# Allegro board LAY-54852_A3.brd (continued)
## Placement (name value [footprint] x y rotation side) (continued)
R1747  10K  [0402_CC]  12.98 62.38 180 top
R1748  1K  [0402_CC]  6.18 68.93 180 top
R1749  0  [0402_CC]  18.67 66.45 180 top
R1750  10K  [0402_CC]  18.67 67.55 0 top
R1751  100  [RC0402_25]  15.26 70.46 180 top
R1752  0  [0402_CC]  6.17 67.77 0 top
R1753  10K  [0402_CC]  13.27 70.44 180 top
R1754  10K  [0402_CC]  6.17 66.59 180 top
R1755  0  [0402_CC]  13.27 69.33 180 top
R1756  22K  [0402_CC]  27.43 54.38 90 top
R1757  0  [0805_CC]  44.99 23.93 180 top
R1758  100K  [0402_CC]  50.08 20.93 180 top
R1759  100K  [0402_CC]  50.08 24.58 0 top
R1760  10K  [0402_CC]  70.29 17.17 90 top
R1761  100K  [0402_CC]  71.4 17.16 270 top
R1762  10K  [0402_CC]  52.37 21.33 90 top
R1763  100K  [0402_CC]  53.68 21.32 90 top
R1764  0  [0402_CC]  68.41 10.11 270 top
R1765  10K  [0402_CC]  67.27 10.09 90 top
R1766  1.2M  [0402_CC]  24.39 36 90 top
R1767  10K  [0402_CC]  79.56 63.2 0 top
R1768  1K  [0402_CC]  24.78 29.61 90 top
R1769  1M  [0402_CC]  26.94 29.6 90 top
R1770  47K  [0603_CC]  26.8 27.54 270 top
R1771  324K  [0402_CC]  25.86 29.61 270 top
R1772  249K  [0402_CC]  25.76 36.03 90 top
R1773  0  [0805_CC]  23.34 16.3 180 top
R1774  0  [0805_CC]  23.29 18.41 180 top
R1775  10K  [0402_CC]  36.98 21.02 270 top
R1776  0  [0402_CC]  30.7 16.02 180 top
R1777  0  [0402_CC]  41.45 18.19 0 top
R1778  0  [0402_CC]  41.45 16.96 0 top
R1779  1.5K  [0402_CC]  95.76 30.99 180 top
R1780  0  [0402_CC]  93.68 30.99 180 top
R1781  10K  [0402_CC]  128.73 30.79 180 top
R1782  41.2K  [RC0402_25]  128.81 36.81 90 top
R1783  100K  [0402_CC]  130.78 30.47 90 top
R1784  0  [0402_CC]  129.64 27.17 270 top
R1785  0  [0402_CC]  128.54 27.18 270 top
R1786  0  [0402_CC]  127.44 27.16 270 top
R1790  1K  [0402_CC]  133.42 20.38 180 top
R1791  1K  [0402_CC]  131.14 19.53 90 top
R1793  0  [0402_CC]  127.97 4.34 90 top
R1795  0  [0402_CC]  107.78 32.49 180 top
R1798  20  [0603_CC]  101.67 20.44 180 top
R1800  0  [0402_CC]  104.35 23.82 270 top
R1801  20  [0603_CC]  106.36 20.3 0 top
R1809  2.20K  [0603_CC]  108.39 16.1 180 top
R1810  10K  [0402_CC]  105.12 18.05 0 top
R1812  120K  [0402_CC]  118.84 29.08 0 bottom
R1813  10K  [0402_CC]  134.34 27.04 0 top
R1814  0  [0402_CC]  10.45 72.17 180 top
R1815  10K  [0402_CC]  8.42 69.88 0 top
R1816  10K  [0402_CC]  10.38 59.14 90 top
R1817  0  [0402_CC]  10.67 45.71 90 top
R1818  0  [0402_CC]  9.6 45.7 90 top
R1819  0  [0402_CC]  8.51 45.68 90 top
R1820  0  [0402_CC]  7.45 45.67 90 top
R1821  10K  [0402_CC]  11.76 45.71 270 top
R1822  0  [0402_CC]  98.4 15.94 270 top
R1823  10K  [0402_CC]  103 18.12 180 top
R1824  10K  [0402_CC]  99.39 76.8 270 bottom
R1825  0  [0402_CC]  100.48 76.81 90 bottom
R1827  10K  [0402_CC]  74.58 71.97 0 top
R1829  0  [0402_CC]  130.9 82.07 0 bottom
S1501  CHS-01TA1  [SW_2P8X5P7_SM]  42.15 61.96 270 top
SW301  M096H-A020RT21A  [SW6_DPDT_M096H_TH]  69.5 1.5 180 top
SW601  CHS-04TA  [SW_CHS_04_A]  41.14 52.96 0 top
SW1401  TL6330AF200Q  [SW4_SPST_4P6X2P8_SM]  26.35 81.54 0 top
SW1402  TL6330AF200Q  [SW4_SPST_4P6X2P8_SM]  33.23 81.54 0 top
TP45  -  [TPAD_050]  76.52 71.99 180 top
TP201  -  [TPAD_015]  79.34 53.58 0 top
TP202  -  [TPAD_015]  79.26 54.27 0 top
TP203  -  [TPAD_015]  79.16 54.84 0 top
TP204  -  [TPAD_015]  79.11 55.47 0 top
TP205  -  [TPAD_015]  79.98 54.99 0 top
TP206  -  [TPAD_015]  79.22 51.44 0 top
TP207  -  [TPAD_015]  79.69 51.98 0 top
TP208  -  [TPAD_015]  79.16 52.48 0 top
TP209  -  [TPAD_015]  79.67 53.01 0 top
TP210  -  [TPAD_015]  79.16 47.24 90 top
TP211  -  [TPAD_015]  79.6 46.66 90 top
TP212  -  [TPAD_015]  79.3 45.96 90 top
TP213  -  [TPAD_015]  80.22 45.53 90 top
TP214  -  [TPAD_015]  79.72 51.02 90 top
TP215  -  [TPAD_015]  79.22 50.32 90 top
TP216  -  [TPAD_015]  79.67 49.7 90 top
TP217  -  [TPAD_015]  79.21 49.11 90 top
TP218  -  [TPAD_015]  73.71 58.29 0 top
TP219  -  [TPAD_015]  77.11 57.04 0 top
TP220  -  [TPAD_015]  93.13 33.47 0 top
TP221  -  [TPAD_015]  96.92 32.69 0 top
TP301  -  [TPAD_020]  43.03 8.74 0 top
TP302  -  [TPAD_050]  46.65 19.99 180 top
TP303  -  [TPAD_020]  44.02 8.06 0 top
TP304  -  [TPAD_050]  47.79 21.02 180 top
TP305  -  [TPAD_020]  70.55 11.66 90 top
TP306  -  [TPAD_020]  70.82 14.14 270 top
TP307  -  [TPAD_020]  70.8 15.77 270 top
TP308  -  [TPAD_020]  65.78 11.19 180 top
TP309  -  [TPAD_020]  65.78 14.45 180 top
TP310  -  [TPAD_020]  65.83 9.9 180 top
TP401  -  [TPAD_020]  20.7 82.18 270 top
TP402  -  [TPAD_020]  85.77 64.2 0 top
TP403  -  [TPAD_020]  52.07 43.43 270 top
TP404  -  [TPAD_020]  88.9 65.79 0 top
TP405  -  [TPAD_020]  51.73 78.11 0 top
TP406  -  [TPAD_020]  58.1 78.09 0 top
TP407  -  [TPAD_015]  87.44 62.04 180 bottom
TP408  -  [TPAD_020]  61.82 67.94 0 top
TP409  -  [TPAD_020]  61.97 64.49 0 top
TP410  -  [TPAD_015]  87.56 65.51 0 top
TP411  -  [TPAD_020]  85.79 63.12 0 top
TP412  -  [TPAD_020]  84.63 63.04 0 top
TP501  -  [TPAD_020]  96.75 42.87 90 top
TP502  -  [TPAD_020]  97.22 40.74 90 top
TP503  -  [TPAD_020]  98.93 38.14 90 top
TP504  -  [TPAD_015]  99.15 39.57 90 top
TP505  -  [TPAD_020]  99.07 40.75 90 top
TP601  TP_35MIL  [TESTPOINT_35MIL]  34.65 50.52 0 top
TP602  TP_35MIL  [TESTPOINT_35MIL]  34.65 52.84 0 top
TP603  TP_35MIL  [TESTPOINT_35MIL]  34.65 54.27 0 top
TP604  TP_35MIL  [TESTPOINT_35MIL]  34.65 57.18 0 top
TP607  TP_35MIL  [TESTPOINT_35MIL]  36.42 44.09 0 top
TP608  TP_35MIL  [TESTPOINT_35MIL]  7.58 71.21 180 top
TP609  TP_35MIL  [TESTPOINT_35MIL]  26.49 11.69 90 top
TP610  TP_35MIL  [TESTPOINT_35MIL]  8.47 53.05 0 top
TP611  TP_35MIL  [TESTPOINT_35MIL]  30.04 11.19 0 top
TP612  TP_35MIL  [TESTPOINT_35MIL]  12.36 53.05 0 top
TP613  TP_35MIL  [TESTPOINT_35MIL]  28.63 11.15 0 top
TP614  TP_35MIL  [TESTPOINT_35MIL]  7.28 53.05 0 top
TP615  TP_35MIL  [TESTPOINT_35MIL]  31.54 10.29 0 top
TP616  TP_35MIL  [TESTPOINT_35MIL]  10.98 53.05 0 top
TP617  TP_35MIL  [TESTPOINT_35MIL]  13.84 53.05 0 top
TP702  TP_35MIL  [TESTPOINT_35MIL]  65.88 42.31 0 top
TP703  TP_35MIL  [TESTPOINT_35MIL]  74.18 34.47 0 top
TP706  TP_35MIL  [TESTPOINT_35MIL]  67.25 20.19 0 top
TP707  TP_35MIL  [TESTPOINT_35MIL]  58.81 20.19 0 top
TP708  TP_35MIL  [TESTPOINT_35MIL]  61.34 41.34 0 top
TP709  TP_35MIL  [TESTPOINT_35MIL]  57.73 33.61 0 top
TP710  TP_35MIL  [TESTPOINT_35MIL]  57.73 35.15 0 top
TP711  TP_35MIL  [TESTPOINT_35MIL]  60.88 38.07 0 top
TP712  TP_35MIL  [TESTPOINT_35MIL]  57.73 36.71 0 top
TP713  TP_35MIL  [TESTPOINT_35MIL]  59.4 38.02 0 top
TP714  TP_35MIL  [TESTPOINT_35MIL]  57.73 32.07 0 top
TP901  TP_35MIL  [TESTPOINT_35MIL]  132.09 30.49 270 top
TP903  -  [TPAD_050]  43.94 32.21 180 top
TP904  -  [TPAD_050]  55.22 37.25 270 top
TP905  -  [TPAD_020]  124.41 4.39 270 top
TP906  -  [TPAD_020]  123.19 4.39 270 top
TP907  -  [TPAD_020]  121.97 4.39 270 top
TP908  -  [TPAD_020]  120.69 4.4 270 top
TP909  -  [TPAD_020]  119.47 4.4 270 top
TP910  -  [TPAD_020]  118.26 4.4 270 top
TP911  -  [TPAD_020]  125.6 4.39 270 top
TP912  -  [TPAD_020]  133.26 2.71 0 top
TP913  -  [TPAD_020]  132.08 2.68 0 top
TP914  -  [TPAD_020]  130.9 2.67 0 top
TP915  TP_35MIL  [TESTPOINT_35MIL]  57.68 30.18 0 top
TP916  TP_35MIL  [TESTPOINT_35MIL]  73.9 24.28 0 top
TP917  -  [TPAD_020]  127.32 2.95 0 top
TP918  -  [TPAD_020]  125.61 3.23 0 top
TP919  -  [TPAD_020]  124.47 3.24 0 top
TP920  -  [TPAD_020]  117.13 4.7 0 top
TP1015  -  [TPAD_020]  43.54 46.99 180 bottom
TP1016  -  [TPAD_020]  40.78 46.85 180 bottom
TP1017  -  [TPAD_020]  39.55 46.84 180 bottom
TP1018  -  [TPAD_020]  38.33 46.85 180 bottom
TP1019  -  [TPAD_020]  38.3 50.75 180 bottom
TP1020  -  [TPAD_020]  38.32 47.93 180 bottom
TP1021  -  [TPAD_020]  44.83 47.03 180 bottom
TP1306  -  [TPAD_020]  13.43 75.48 180 top
TP1401  -  [TPAD_020]  115.44 66.22 90 top
TP1402  TEST POINT  [TP_TH_018]  118.84 70.97 90 top
TP1403  TEST POINT  [TP_TH_018]  120.85 70.97 90 top
TP1404  TEST POINT  [TP_TH_018]  122.74 71.05 90 top
TP1405  -  [TPAD_020]  2.1 29.8 0 top
TP1406  -  [TPAD_020]  2.1 28.58 0 top
TP1407  -  [TPAD_020]  2.1 22.4 90 top
TP1408  -  [TPAD_020]  14.17 36.71 0 top
TP1412  -  [TPAD_020]  8.3 7.53 0 top
TP1413  -  [TPAD_020]  15.43 36.71 270 top
TP1414  -  [TPAD_020]  12.4 36.71 270 top
TP1415  -  [TPAD_020]  11.18 36.71 270 top
TP1416  -  [TPAD_020]  9.51 36.71 270 top
TP1417  -  [TPAD_020]  8.29 36.71 270 top
TP1418  -  [TPAD_020]  7.07 36.71 270 top
TP1419  -  [TPAD_020]  5.85 36.71 270 top
TP1420  -  [TPAD_020]  2.1 27.44 0 top
TP1421  -  [TPAD_020]  2.1 26.22 0 top
TP1422  -  [TPAD_020]  2.1 25 0 top
TP1423  -  [TPAD_020]  2.1 23.78 0 top
TP1424  -  [TPAD_020]  24.8 57.32 180 top
TP1425  -  [TPAD_020]  24.8 58.54 180 top
TP1426  -  [TPAD_020]  24.8 59.76 180 top
TP1427  -  [TPAD_020]  23.47 59.8 180 top
TP1428  -  [TPAD_020]  16.8 57.6 180 top
TP1429  -  [TPAD_020]  20.63 30.17 180 top
TP1430  TP_35MIL  [TESTPOINT_35MIL]  4.81 48.38 180 top
TP1431  TP_35MIL  [TESTPOINT_35MIL]  2.59 37.59 180 top
TP1432  TP_35MIL  [TESTPOINT_35MIL]  4.03 37.58 180 top
TP1701  -  [TPAD_050]  25.84 68.75 270 top
TP1901  5123  [TP_TH_063]  15.77 41.98 0 top
TP1902  -  [TPAD_050]  35.35 70.17 0 top
TP1903  -  [TPAD_050]  11.58 56.13 0 top
TP1904  -  [TPAD_050]  93.13 22.86 0 top
TP1905  5123  [TP_TH_063]  76.18 39.98 0 top
TP1907  -  [TPAD_050]  19.65 34.18 0 top
TP1908  -  [TPAD_050]  55.32 33.22 0 top
TP1909  -  [TPAD_050]  46.25 71.53 0 top
TP1912  -  [TPAD_020]  20.63 27.73 180 top
TP1913  -  [TPAD_020]  20.6 29.03 180 top
TP1914  -  [TPAD_050]  131.7 41.78 0 top
TP1919  -  [TPAD_050]  128.91 39.88 180 top
TP1920  -  [TPAD_020]  128.37 19.63 180 top
TP1921  -  [TPAD_020]  124.88 20.03 180 top
TP1922  -  [TPAD_020]  83.75 44.28 0 top
TP1923  -  [TPAD_020]  81.97 44.26 0 top
TP1924  -  [TPAD_020]  81.16 63.2 0 top
TP1925  -  [TPAD_050]  22.12 13.15 180 top
TP1926  -  [TPAD_020]  38.96 20.98 90 top
TP1927  -  [TPAD_020]  40.13 15.17 90 top
TP1928  -  [TPAD_020]  27.87 9.02 0 top
TP1929  -  [TPAD_020]  34.02 16.65 0 top
TP1930  -  [TPAD_020]  31.55 8.87 0 top
TP1931  -  [TPAD_020]  22.46 7.33 0 top
TP1932  -  [TPAD_020]  34.27 20.52 90 top
TP1933  -  [TPAD_020]  84.33 31.98 270 top
TP1934  -  [TPAD_020]  134.89 4.32 270 top
TP1935  -  [TPAD_020]  133.67 4.32 270 top
TP1936  -  [TPAD_020]  129.66 2.9 0 top
TP1937  -  [TPAD_020]  128.55 2.93 0 top
TP1942  -  [TPAD_050]  111.2 25.4 180 top
TP1943  -  [TPAD_050]  111.2 20.39 180 top
TP1944  -  [TPAD_050]  111.2 23.73 180 top
TP1945  -  [TPAD_050]  111.2 22.06 180 top
TP1948  -  [TPAD_020]  103.09 32.24 0 top
TP1950  -  [TPAD_020]  103.05 31.08 0 top
TP1951  -  [TPAD_020]  17.74 35.49 0 top
TP1952  -  [TPAD_020]  16.78 36.74 0 top
TP1953  -  [TPAD_020]  99.13 31.58 0 top
TP1954  TP_35MIL  [TESTPOINT_35MIL]  116.93 72.49 0 top
TVS901  ESD5B5.0ST1G  [DIODE2_SOD523]  51.22 6.8 90 top
TVS1201  ESD5B5.0ST1G  [DIODE2_SOD523]  108.35 14.61 180 top
TVS1202  ESD5B5.0ST1G  [DIODE2_SOD523]  102.64 14.38 180 top
TVS1203  ESD5B5.0ST1G  [DIODE2_SOD523]  99.66 14.37 0 top
TVS1204  ESD5B5.0ST1G  [DIODE2_SOD523]  105.38 14.37 0 top
TVS1401  ESD5B5.0ST1G  [DIODE2_SOD523]  12.79 9.96 270 top
U58  AP22814AW5  [SOT25]  78.13 74.32 0 bottom
U101  SKT BGA 208 + MIMX9322XVXxMAB  [SKT_BGA208_0P5_17P725SQ_ELAST]  88.24 52.71 0 top
U201  MT53E1G16D1FW-046 AAT:A  [BGA200_0P65X0P8_10X14P5]  71.21 51.21 270 top
U301  PTN5110  [HX2QFN16_0P4_2P7X2P7]  68.24 13.24 270 top
U302  NX20P5090UK  [WLCSP15_0P5_1P57X2P59]  47.44 23.73 180 top
U303  NX20P0407  [WLCSP12_0P4_1P3X1P7MM_SMDP]  72.01 11.56 180 top
U401  PTN5110  [HX2QFN16_0P4_2P7X2P7]  37.72 17.63 90 top
U402  NX20P3483UK  [WLCSP42_0P4_2P94X2P54_SMDP]  26.51 16.95 180 top
U403  PCMF1USB3S  [WLCSP5_0P4_0P82X1P22]  29.39 9.5 180 top
U404  SGM8709YN5G  [SOT-23-5]  24.62 32.86 0 top
U405  TLV76033DBZR  [SOT-23]  30.92 35.79 270 top
U411  NX20P0407  [WLCSP12_0P4_1P3X1P7MM_SMDP]  34.14 18.77 90 top
U501  SDINBDA6-16G-I  [FBGA153_0P5_11P5X13]  105.73 41.15 0 top
U502  PUSB3FR4  [XSON10_0P5_1P1X2P6MM]  89.15 22.45 90 top
U503  PUSB3FR4  [XSON10_0P5_1P1X2P6MM]  84.71 22.45 90 top
U701  PCA9451AHNY  [HVQFN56_0P4_7X7_EP4P7MM]  65.11 30.55 0 top
U801  PCAL6524HEAZ  [UQFN32_0P5_5X5_EP3X3]  109.68 61.57 90 top
U802  74AUP1G07GW  [SC70-5]  100.32 65.34 0 top
U803  TMUX1574RSVR  [PQFN16_0P4_2P65X1P85]  131.22 71.3 90 top
U804  TMUX1574RSVR  [PQFN16_0P4_2P65X1P85]  100.89 71.53 180 top
U805  TMUX1574RSVR  [PQFN16_0P4_2P65X1P85]  110.84 71.01 180 top
U901  MP8759GD  [QFN12_0P5_3P1X2P1]  39.49 34.57 180 top
U902  DML3006LFDS-7  [DFN2020_0P5_SQ2]  51.76 39.09 270 top
U904  74AVC4T3144  [XQFN12_0P4_1P8X2P1]  128.47 24.62 270 top
U905  TXB0304RUTR  [UQFN12_1P7X2MM]  121.76 28.98 270 bottom
U906  TXB0304RUTR  [UQFN12_1P7X2MM]  121.75 28.98 90 top
U908  NTS0104GU12  [XQFN12_0P4_1P8X2P1]  116.17 24.18 180 bottom
U915  P3T1085UK  [WLCSP6_0P4_0P84X1P18]  116.07 77.22 180 bottom
U1004  PCF2131  [SO16_0P5_3P5X4P5_MM]  41.87 50.79 180 bottom
U1202  AP22818AKBWT  [SOT23-5]  112.19 30.54 0 top
U1301  SPK0641HT4H-1  [LGA8_3P1X4P1MM_SPK0641]  4.31 7.91 0 top
U1302  SPK0641HT4H-1  [LGA8_3P1X4P1MM_SPK0641]  75.15 7.91 0 top
U1304  SPK0641HT4H-1  [LGA8_3P1X4P1MM_SPK0641]  4.31 78.76 0 top
U1305  SPK0641HT4H-1  [LGA8_3P1X4P1MM_SPK0641]  75.15 78.76 0 top
U1306  NCP161ASN180T1G  [SOT-23-5]  10.95 76.71 180 top
U1307  74LV1T34GWH  [SC70-5]  18.77 75.97 0 top
U1308  74LV1T34GWH  [SC70-5]  19.3 71.14 0 top
U1309  74LV1T34GWH  [SC70-5]  20.16 79.84 0 top
U1401  LSM6DSOXTR  [LGA14_0P5_3X2P5]  120.52 67.23 90 top
U1403  PCMF1USB3S  [WLCSP5_0P4_0P82X1P22]  15.3 9.5 180 top
U1404  74AVC4T245GU  [XQFN16_0P4_2P7X1P9]  29.7 62.63 270 top
U1405  93LC56BT  [SOT23-6]  3.72 43.07 180 top
U1406  74HC3G06DC  [SSOP8_DCU]  16.59 61.54 90 top
U1407  74AUP1G126GM  [UDFN6_1X1P5MM]  13.27 67.47 180 top
U1408  74AVC4T3144  [XQFN12_0P4_1P8X2P1]  22.25 39.02 90 top
U1409  PCA9655EMTTXG  [QFN24_4X4_EP2P25MM]  21.21 56.5 90 top
U1410  RT9193  [SOT23-5]  6.65 13.29 90 top
U1501  TJA1057GT/3  [SO8_1P27_4X5]  29.62 72.3 270 top
U1702  TMUX1574RSVR  [PQFN16_0P4_2P65X1P85]  24.97 71.8 270 top
U1706  FT4232H  [LQFP64_0P5_10X10]  11.25 27.62 90 top
U1707  74LV1T126GVH  [SOT753_5P_1P7X3P1MM]  135.13 41.81 0 top
U1708  FPF1504  [WLCSP4_0P5_0P99X0P99]  129.67 44.45 180 top
U1709  WM8962BECSN/R  [BGA49_0P5_3P62X4]  104.02 27.82 180 top
U1710  MP2147GD  [QFN12_0P5_2X3MM_EP]  132.54 33.2 270 top
U1712  RTL8211FDI-VD-CG  [QFN40_0P4_5X5MM]  88.77 31.22 90 top
U1713  74AVC4T245GU  [XQFN16_0P4_2P7X1P9]  10.58 48.71 90 top
U1714  AP22818AKBWT  [SOT23-5]  97.12 78.24 0 bottom
X1401  12 MHz  [XTAL_4_3P3X2P6MM]  3.83 17.63 0 top
Y401  24MHZ  [XTLOSC4_3P2X2P5MM_SM]  90.04 63.48 180 bottom
Y501  25MHz  [XTL4_2P5X2MM_SM]  80.52 30.58 90 top

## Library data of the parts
BH901 BH1901-BH1904 = MOUNT_HOLE
BT1001 = BATTERY
C10 C22 C23 C38 C101 C102 C104-C111 C115 C116 C118 C119 C129-C133 C136-C140 C142-C146 C151-C153 C155 C201-C222 C301 C304-C307 C309 C401-C414 C418 C501-C509 C511 C512 C514 C516-C518 C701-C731 C801-C803 C806 C807 C809 C901-C904 C906 C908 C910-C918 C921 C923 C930-C933 C956 C1019 C1020 C1022-C1024 C1201 C1202 C1204 C1205 C1207-C1210 C1217-C1219 C1221 C1223 C1224 C1227 C1230 C1231 C1301-C1303 C1307 C1309 C1317 C1319 C1321 C1322 C1324 C1325 C1402 C1405-C1411 C1413-C1423 C1425 C1427 C1429 C1431-C1433 C1435 C1437 C1448 C1449 C1460-C1462 C1501-C1509 C1703 C1704 C1720 C1722-C1725 C1727-C1735 C1737 C1740 C1742-C1757 C1761-C1765 C1769-C1772 C1787-C1789 C1792 = CAP_NP
C302 C303 C905 = CAP_POL
C510 C519-C521 C1741 = CAP_NP: room: RGMII_PHY
C513 C515 C804 C805 C808 C907 C920 C922 C928 C955 C1021 C1304 C1308 C1310 C1318 C1320 C1323 C1401 C1403 C1404 C1412 C1424 C1426 C1434 C1436 C1719 C1721 C1726 C1738 C1739 = CAP_NP: tolerance: 10%
C1428 C1430 = CAP_NP: tolerance: 5%; room: RGMII_PHY
C1736 = MOT_CAP
D301 D401 D402 D1011 D1012 D1401 = DIODE
D302 D901 = ZDIODE
D601 D902 D1403-D1406 D1410-D1415 D1501 D1502 D1705 D1706 = LED
D1003 D1004 TVS901 TVS1201-TVS1204 TVS1401 = DIODE_TVS_BIDIR
D1005-D1010 = DIODE_BIDIR
D1402 = LED_GPLY6900
D1407-D1409 D1703 D1704 = DIODE_SCHTKY
D1503 = ESD_DIODE_2LINE
F301 F401 = FUSE
J301 = USB6_TYPEC_SH4_1_A
J501 = RJ45_2 DUAL_LED_10P
J901 J1710 = CONN_HDR_2X1
J1002 = CONN_MICRO_SDCARD
J1101 J1708 = USB24_TYPEC_SH4
J1201 = CON_KJ366EYS_AUDIOJACK_6P
J1401 = CONN_HDR_20X2
J1403 = CONN_HDR_3X2
J1405 J1406 = CONN_HDR_4X2
J1501 = CONN_HDR_4X1
J1704 = CONN_HDR_5X2
J1707 = CON_67_FEMALE_RA_B
L102 = INDUCTOR_FERRITE_0
L501 L502 L1202 L1203 L1205 L1301 L1401-L1405 L1702-L1704 = BEAD_0
L701-L704 L1705 = INDUCTOR: tolerance: 20%
L705 L706 L901 = INDUCTOR
L1201 = BEAD_0: room: RGMII_PHY
L1501 = DLW43
Q301 Q302 Q901 Q902 Q1401-Q1405 Q1407-Q1411 = NX3008NBKW_SOT323
Q1406 = MOSFET_P
QZ401 QZ701 = XTAL
R14 R16 R64 R65 R102 R111 R163 R164 R201 R204 R205 R207-R211 R213 R301-R313 R350-R360 R401-R421 R423 R424 R431-R434 R501-R527 R529-R531 R601-R613 R701-R720 R723 R741-R746 R751 R752 R801 R802 R804-R813 R817 R818 R820-R833 R835-R841 R845 R850-R856 R858 R860-R863 R871 R901-R915 R917-R919 R922-R924 R930-R932 R935 R936 R938 R941-R954 R956-R959 R1008 R1009 R1015-R1018 R1051-R1057 R1060-R1065 R1072-R1085 R1202-R1209 R1211 R1212 R1214 R1216 R1218-R1222 R1302 R1303 R1318 R1322 R1324-R1327 R1329 R1330 R1333 R1401-R1448 R1450-R1461 R1464 R1465 R1467-R1470 R1485-R1490 R1501-R1512 R1703-R1706 R1717-R1721 R1723 R1724 R1726-R1737 R1739-R1767 R1769-R1778 R1780-R1786 R1790 R1791 R1793 R1795 R1798 R1800 R1801 R1809 R1810 R1812-R1825 R1827 R1829 = RES
R1449 R1462 R1463 R1738 = RES: tolerance: 1%
R1768 = RES: tolerance: 5%
R1779 = RES: room: RGMII_PHY
S1501 = SW-SPST_A
SW301 = SW_DPDT_3
SW601 = CHS-04TA_SW
SW1401 SW1402 = SW_PB_ESW
TP45 TP301-TP310 TP401-TP406 TP408 TP409 TP411 TP412 TP501-TP503 TP505 TP903-TP914 TP917-TP920 TP1015-TP1021 TP1306 TP1401-TP1408 TP1412-TP1429 TP1701 TP1902-TP1904 TP1907-TP1909 TP1912-TP1914 TP1919-TP1937 TP1942-TP1945 TP1948 TP1950-TP1953 = TESTLOOP
TP201-TP221 TP407 TP410 TP504 = TestLoop
TP601-TP604 TP607-TP617 TP702 TP703 TP706-TP714 TP901 TP915 TP916 TP1430-TP1432 TP1954 = T POINT R: Tolerance: TOLERANCE; User Part Number: 510-75618
TP1901 TP1905 = T POINT TH
U58 = AP22816_SOT25_5P
U101 = MIMX9322XVXxMAB_BGA208
U201 = MT53B768M32D4NQ_200P
U301 U401 = PTN5110_QFN16
U302 = NX20P5090UK_15P_A
U303 U411 = NX20P0407_WLCSP12_A
U402 = NX20P3483UK_42P
U403 U1403 = PESD1USB30_5P
U404 = SGM8709YN5G
U405 = LM3480IM3
U501 = SDINBDA6_32G_I_VFBGA_153P
U502 U503 = DIODE_ESD_4CH_10P_A_1
U701 = PCA9451AHNY
U801 = PCAL6524HE_QFN
U802 = 74AUP1G07GW
U803-U805 U1702 = TMUX1574RSVR_A
U901 = MP8759GD_QFN12P
U902 = DML3006LFDS-7_A
U904 U1408 = 74AVC4T3144_12P_A
U905 U906 = TXB0304RUT_12P_B
U908 = NTS0104GU12_12P
U915 = P3T2108_6P
U1004 = PCF2131_4
U1202 U1714 = AP22818AKB
U1301 U1302 U1304 U1305 = SPK0641HT4H_8P_A
U1306 = NCP161ASN180T1G_A
U1307-U1309 = 74LV1T34GWH_TSSOP6
U1401 = LSM6DSO_LGA14P
U1404 U1713 = 74AVC4T245GU_XQFN16
U1405 = 93AA56BT_SOT23-6
U1406 = 74HC3G06DC
U1407 = 74AUP1G126GM
U1409 = PCA9655EMTTXG_WQFN24_A
U1410 = RT9193-33PB
U1501 = TJA1057GT3_8P
U1706 = FT4232HL_LQFP64
U1707 = 74LV1T126GVH
U1708 = FPF1504UCX_CSP4_A
U1709 = WM8962_BGA_49P_CUST
U1710 = MP2147GD_QFN_11P
U1712 = RTL8211FDI-40P
X1401 Y401 Y501 = XTAL_13

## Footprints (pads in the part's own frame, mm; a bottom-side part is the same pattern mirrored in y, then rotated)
0201_CC
  rect 0.305x0.305 smd: 1(-0.267,0) 2(0.267,0)
0402_CC
  rect 0.457x0.508 smd: 1(-0.375,0) 2(0.375,0)
0603_CC
  rect 0.711x0.838 smd: 1(-0.65,0) 2(0.65,0)
0805_CC
  rect 0.94x1.346 smd: 1(-0.78,0) 2(0.78,0)
1206_CC
  rect 0.94x1.702 smd: 1(-1.4,0) 2(1.4,0)
1210_CC
  rect 0.94x2.591 smd: 1(-1.4,0) 2(1.4,0)
BATTERY_4P8SQ_S
  custom 0.325x0.325 smd: 1(1.755,1.755)
  rect 3.505x1.016 smd: 2(0.508,-2.032)
BGA49_0P5_3P62X4
  round 0.254 smd: A1(-1.5,1.5) A2(-1,1.5) A3(-0.5,1.5) A4(0,1.5) A5(0.5,1.5) A6(1,1.5) A7(1.5,1.5) B1(-1.5,1) B2(-1,1) B3(-0.5,1) B4(0,1) B5(0.5,1) B6(1,1) B7(1.5,1) C1(-1.5,0.5) C2(-1,0.5) C3(-0.5,0.5) C4(0,0.5) C5(0.5,0.5) C6(1,0.5) C7(1.5,0.5) D1(-1.5,0) D2(-1,0) D3(-0.5,0) D4(0,0) D5(0.5,0) D6(1,0) D7(1.5,0) E1(-1.5,-0.5) E2(-1,-0.5) E3(-0.5,-0.5) E4(0,-0.5) E5(0.5,-0.5) E6(1,-0.5) E7(1.5,-0.5) F1(-1.5,-1) F2(-1,-1) F3(-0.5,-1) F4(0,-1) F5(0.5,-1) F6(1,-1) F7(1.5,-1) G1(-1.5,-1.5) G2(-1,-1.5) G3(-0.5,-1.5) G4(0,-1.5) G5(0.5,-1.5) G6(1,-1.5) G7(1.5,-1.5)
BGA200_0P65X0P8_10X14P5
  round 0.356 smd: A1(-4.4,6.825) A2(-3.6,6.825) A3(-2.8,6.825) A4(-2,6.825) A5(-1.2,6.825) A8(1.2,6.825) A9(2,6.825) A10(2.8,6.825) A11(3.6,6.825) A12(4.4,6.825) AA1(-4.4,-6.175) AA2(-3.6,-6.175) AA3(-2.8,-6.175) AA4(-2,-6.175) AA5(-1.2,-6.175) AA8(1.2,-6.175) AA9(2,-6.175) AA10(2.8,-6.175) AA11(3.6,-6.175) AA12(4.4,-6.175) AB1(-4.4,-6.825) AB2(-3.6,-6.825) AB3(-2.8,-6.825) AB4(-2,-6.825) AB5(-1.2,-6.825) AB8(1.2,-6.825) AB9(2,-6.825) AB10(2.8,-6.825) AB11(3.6,-6.825) AB12(4.4,-6.825) B1(-4.4,6.175) B2(-3.6,6.175) B3(-2.8,6.175) B4(-2,6.175) B5(-1.2,6.175) B8(1.2,6.175) B9(2,6.175) B10(2.8,6.175) B11(3.6,6.175) B12(4.4,6.175) C1(-4.4,5.525) C2(-3.6,5.525) C3(-2.8,5.525) C4(-2,5.525) C5(-1.2,5.525) C8(1.2,5.525) C9(2,5.525) C10(2.8,5.525) C11(3.6,5.525) C12(4.4,5.525) D1(-4.4,4.875) D2(-3.6,4.875) D3(-2.8,4.875) D4(-2,4.875) D5(-1.2,4.875) D8(1.2,4.875) D9(2,4.875) D10(2.8,4.875) D11(3.6,4.875) D12(4.4,4.875) E1(-4.4,4.225) E2(-3.6,4.225) E3(-2.8,4.225) E4(-2,4.225) E5(-1.2,4.225) E8(1.2,4.225) E9(2,4.225) E10(2.8,4.225) E11(3.6,4.225) E12(4.4,4.225) F1(-4.4,3.575) F2(-3.6,3.575) F3(-2.8,3.575) F4(-2,3.575) F5(-1.2,3.575) F8(1.2,3.575) F9(2,3.575) F10(2.8,3.575) F11(3.6,3.575) F12(4.4,3.575) G1(-4.4,2.925) G2(-3.6,2.925) G3(-2.8,2.925) G4(-2,2.925) G5(-1.2,2.925) G8(1.2,2.925) G9(2,2.925) G10(2.8,2.925) G11(3.6,2.925) G12(4.4,2.925) H1(-4.4,2.275) H2(-3.6,2.275) H3(-2.8,2.275) H4(-2,2.275) H5(-1.2,2.275) H8(1.2,2.275) H9(2,2.275) H10(2.8,2.275) H11(3.6,2.275) H12(4.4,2.275) J1(-4.4,1.625) J2(-3.6,1.625) J3(-2.8,1.625) J4(-2,1.625) J5(-1.2,1.625) J8(1.2,1.625) J9(2,1.625) J10(2.8,1.625) J11(3.6,1.625) J12(4.4,1.625) K1(-4.4,0.975) K2(-3.6,0.975) K3(-2.8,0.975) K4(-2,0.975) K5(-1.2,0.975) K8(1.2,0.975) K9(2,0.975) K10(2.8,0.975) K11(3.6,0.975) K12(4.4,0.975) N1(-4.4,-0.975) N2(-3.6,-0.975) N3(-2.8,-0.975) N4(-2,-0.975) N5(-1.2,-0.975) N8(1.2,-0.975) N9(2,-0.975) N10(2.8,-0.975) N11(3.6,-0.975) N12(4.4,-0.975) P1(-4.4,-1.625) P2(-3.6,-1.625) P3(-2.8,-1.625) P4(-2,-1.625) P5(-1.2,-1.625) P8(1.2,-1.625) P9(2,-1.625) P10(2.8,-1.625) P11(3.6,-1.625) P12(4.4,-1.625) R1(-4.4,-2.275) R2(-3.6,-2.275) R3(-2.8,-2.275) R4(-2,-2.275) R5(-1.2,-2.275) R8(1.2,-2.275) R9(2,-2.275) R10(2.8,-2.275) R11(3.6,-2.275) R12(4.4,-2.275) T1(-4.4,-2.925) T2(-3.6,-2.925) T3(-2.8,-2.925) T4(-2,-2.925) T5(-1.2,-2.925) T8(1.2,-2.925) T9(2,-2.925) T10(2.8,-2.925) T11(3.6,-2.925) T12(4.4,-2.925) U1(-4.4,-3.575) U2(-3.6,-3.575) U3(-2.8,-3.575) U4(-2,-3.575) U5(-1.2,-3.575) U8(1.2,-3.575) U9(2,-3.575) U10(2.8,-3.575) U11(3.6,-3.575) U12(4.4,-3.575) V1(-4.4,-4.225) V2(-3.6,-4.225) V3(-2.8,-4.225) V4(-2,-4.225) V5(-1.2,-4.225) V8(1.2,-4.225) V9(2,-4.225) V10(2.8,-4.225) V11(3.6,-4.225) V12(4.4,-4.225) W1(-4.4,-4.875) W2(-3.6,-4.875) W3(-2.8,-4.875) W4(-2,-4.875) W5(-1.2,-4.875) W8(1.2,-4.875) W9(2,-4.875) W10(2.8,-4.875) W11(3.6,-4.875) W12(4.4,-4.875) Y1(-4.4,-5.525) Y2(-3.6,-5.525) Y3(-2.8,-5.525) Y4(-2,-5.525) Y5(-1.2,-5.525) Y8(1.2,-5.525) Y9(2,-5.525) Y10(2.8,-5.525) Y11(3.6,-5.525) Y12(4.4,-5.525)
CASE_D_AL
  rect 3.556x1.575 smd: 1(-2.642,0) 2(2.642,0)
CC0402_25
  round 0.635 smd: 1(-0.508,0) 2(0.508,0)
CC0402_TOL0P15
  rect 0.457x0.61 smd: 1(-0.475,0) 2(0.475,0)
CC0603
  rect 0.991x0.813 smd: 1(-0.686,0) 2(0.686,0)
CC0603_OV
  oval 0.889x1.143 smd: 1(-0.762,0) 2(0.762,0)
CC0805_OV
  oval 0.889x1.524 smd: 1(-0.965,0) 2(0.965,0)
CC1210
  rect 1.778x2.845 smd: 1(-1.397,0) 2(1.397,0)
CCE8P3X8P3
  rect 4.394x1.905 smd: 1(-2.807,0) 2(2.807,0)
CON1X4_2MM_TH_303H
  rect 1.448x1.448 hole 0.813: 1(0,0)
  round 1.448 hole 0.813: 2(-2,0) 3(-4,0) 4(-6,0)
CON2_2P5_7P96X5P96_TH
  rect 1.905x1.905 hole 1.397: 1(0,0)
  round 1.905 hole 1.397: 2(0,-2.5)
CON6_AUDIOJACK_RA_TH
  round 0 hole 1.499 unplated: (0.4,2.7) (7.4,2.7)
  oval 2.108x1.092 hole 1.499x0.508: 1(0,0) 2(0,5.15)
  rect 1.6x1.803 smd: 3(9.4,-0.8) 4(9.4,6.2) 5(6.2,6.2) 6(6.2,-0.8)
CON9_SDCARD_1P1MM
  round 0 hole 0.991 unplated: (-4.95,-3.25) (3.05,-3.25)
  rect 0.711x1.6 smd: 1(2.25,7.25) 2(1.15,7.25) 3(0.05,7.25) 4(-1.05,7.25) 5(-2.15,7.25) 6(-3.25,7.25) 7(-4.35,7.25) 8(-5.45,7.25) 9(-6.55,7.25)
  rect 1.194x1.6 smd: 10(-7.75,6.65)
  rect 1.194x2.21 smd: 11(-7.75,-2.85) 12(7.75,-2.85)
  rect 1.6x1.397 smd: 13(6.85,6.75)
CON24_USB_TYPEC_RA_SMT_TH_2P2L
  round 0 hole 0.66 unplated: (-6.775,-0.7) (0.675,-0.7)
  rect 0.305x0.711 smd: A1(-5.8,1.11) A2(-5.3,1.11) A3(-4.8,1.11) A4(-4.3,1.11) A5(-3.8,1.11) A6(-3.3,1.11) A7(-2.8,1.11) A8(-2.3,1.11) A9(-1.8,1.11) A10(-1.3,1.11) A11(-0.8,1.11) A12(-0.3,1.11)
  round 0.66 hole 0.406: B1(0,0) B2(-0.65,-0.7) B3(-1.45,-0.7) B4(-1.85,0) B5(-2.25,-0.7) B6(-2.65,0) B7(-3.45,0) B8(-3.85,-0.7) B9(-4.25,0) B10(-4.65,-0.7) B11(-5.45,-0.7) B12(-6.1,0)
  oval 1.016x1.6 hole 0.508x1.118: SH1(-7.55,0.81) SH2(1.45,0.81)
  oval 1.016x1.803 hole 0.508x1.295: SH3(-7.55,-4.8) SH4(1.45,-4.8)
CON_2X4_SKT_100_SM
  rect 2.235x1.016 smd: 1(2.826,3.81) 2(-2.826,3.81) 3(2.826,1.27) 4(-2.826,1.27) 5(2.826,-1.27) 6(-2.826,-1.27) 7(2.826,-3.81) 8(-2.826,-3.81)
CON_75_0P5_22X9_RA1
  rect 1.194x2.743 smd: (-10.35,2.825) (10.35,2.825)
  round 0 hole 1.092 unplated: (-10,-1.675)
  round 0 hole 1.6 unplated: (10,-1.675)
  rect 0.305x2.032 smd: 1(-9.25,3.36) 2(-9,-3.71) 3(-8.75,3.36) 4(-8.5,-3.71) 5(-8.25,3.36) 6(-8,-3.71) 7(-7.75,3.36) 8(-7.5,-3.71) 9(-7.25,3.36) 10(-7,-3.71) 11(-6.75,3.36) 12(-6.5,-3.71) 13(-6.25,3.36) 14(-6,-3.71) 15(-5.75,3.36) 16(-5.5,-3.71) 17(-5.25,3.36) 18(-5,-3.71) 19(-4.75,3.36) 20(-4.5,-3.71) 21(-4.25,3.36) 22(-4,-3.71) 23(-3.75,3.36) 32(-1.5,-3.71) 33(-1.25,3.36) 34(-1,-3.71) 35(-0.75,3.36) 36(-0.5,-3.71) 37(-0.25,3.36) 38(0,-3.71) 39(0.25,3.36) 40(0.5,-3.71) 41(0.75,3.36) 42(1,-3.71) 43(1.25,3.36) 44(1.5,-3.71) 45(1.75,3.36) 46(2,-3.71) 47(2.25,3.36) 48(2.5,-3.71) 49(2.75,3.36) 50(3,-3.71) 51(3.25,3.36) 52(3.5,-3.71) 53(3.75,3.36) 54(4,-3.71) 55(4.25,3.36) 56(4.5,-3.71) 57(4.75,3.36) 58(5,-3.71) 59(5.25,3.36) 60(5.5,-3.71) 61(5.75,3.36) 62(6,-3.71) 63(6.25,3.36) 64(6.5,-3.71) 65(6.75,3.36) 66(7,-3.71) 67(7.25,3.36) 68(7.5,-3.71) 69(7.75,3.36) 70(8,-3.71) 71(8.25,3.36) 72(8.5,-3.71) 73(8.75,3.36) 74(9,-3.71) 75(9.25,3.36)
CON_RJ45_10_2LED_TH
  round 0 hole 3.251 unplated: (-11.43,8.89) (0,8.89)
  rect 1.499x1.499 hole 0.889: 1(0,0)
  round 1.499 hole 0.889: 2(-1.27,2.54) 3(-2.54,0) 4(-3.81,2.54) 5(-5.08,0) 6(-6.35,2.54) 7(-7.62,0) 8(-8.89,2.54) 9(-10.16,0) 10(-11.43,2.54)
  round 1.651 hole 1.016: 11(0.915,12.97) 12(-1.625,12.97) 13(-9.805,12.97) 14(-12.345,12.97)
  round 2.642 hole 1.6: SH1(2.03,5.84) SH2(-13.46,5.84)
DFN2020_0P5_SQ2
  rect 0.483x0.279 smd: 1(-0.91,0.75) 2(-0.91,0.25) 3(-0.91,-0.25) 4(-0.91,-0.75) 5(0.91,-0.75) 6(0.91,-0.25)
  custom 0.12x0.12 smd: 7(0.91,0.75)
  rect 0.914x1.6 smd: 8(0,0)
DIODE2_SOD523
  rect 0.61x0.813 smd: 1(-0.85,0) 2(0.85,0)
DSN0603-2
  rect 0.152x0.254 smd: 1(-0.2,0) 2(0.2,0)
FBGA153_0P5_11P5X13
  round 0.254 smd: A1(-3.25,3.25) A2(-2.75,3.25) A3(-2.25,3.25) A4(-1.75,3.25) A5(-1.25,3.25) A6(-0.75,3.25) A7(-0.25,3.25) A8(0.25,3.25) A9(0.75,3.25) A10(1.25,3.25) A11(1.75,3.25) A12(2.25,3.25) A13(2.75,3.25) A14(3.25,3.25) B1(-3.25,2.75) B2(-2.75,2.75) B3(-2.25,2.75) B4(-1.75,2.75) B5(-1.25,2.75) B6(-0.75,2.75) B7(-0.25,2.75) B8(0.25,2.75) B9(0.75,2.75) B10(1.25,2.75) B11(1.75,2.75) B12(2.25,2.75) B13(2.75,2.75) B14(3.25,2.75) C1(-3.25,2.25) C2(-2.75,2.25) C3(-2.25,2.25) C4(-1.75,2.25) C5(-1.25,2.25) C6(-0.75,2.25) C7(-0.25,2.25) C8(0.25,2.25) C9(0.75,2.25) C10(1.25,2.25) C11(1.75,2.25) C12(2.25,2.25) C13(2.75,2.25) C14(3.25,2.25) D1(-3.25,1.75) D2(-2.75,1.75) D3(-2.25,1.75) D4(-1.75,1.75) D12(2.25,1.75) D13(2.75,1.75) D14(3.25,1.75) E1(-3.25,1.25) E2(-2.75,1.25) E3(-2.25,1.25) E5(-1.25,1.25) E6(-0.75,1.25) E7(-0.25,1.25) E8(0.25,1.25) E9(0.75,1.25) E10(1.25,1.25) E12(2.25,1.25) E13(2.75,1.25) E14(3.25,1.25) F1(-3.25,0.75) F2(-2.75,0.75) F3(-2.25,0.75) F5(-1.25,0.75) F10(1.25,0.75) F12(2.25,0.75) F13(2.75,0.75) F14(3.25,0.75) G1(-3.25,0.25) G2(-2.75,0.25) G3(-2.25,0.25) G5(-1.25,0.25) G10(1.25,0.25) G12(2.25,0.25) G13(2.75,0.25) G14(3.25,0.25) H1(-3.25,-0.25) H2(-2.75,-0.25) H3(-2.25,-0.25) H5(-1.25,-0.25) H10(1.25,-0.25) H12(2.25,-0.25) H13(2.75,-0.25) H14(3.25,-0.25) J1(-3.25,-0.75) J2(-2.75,-0.75) J3(-2.25,-0.75) J5(-1.25,-0.75) J10(1.25,-0.75) J12(2.25,-0.75) J13(2.75,-0.75) J14(3.25,-0.75) K1(-3.25,-1.25) K2(-2.75,-1.25) K3(-2.25,-1.25) K5(-1.25,-1.25) K6(-0.75,-1.25) K7(-0.25,-1.25) K8(0.25,-1.25) K9(0.75,-1.25) K10(1.25,-1.25) K12(2.25,-1.25) K13(2.75,-1.25) K14(3.25,-1.25) L1(-3.25,-1.75) L2(-2.75,-1.75) L3(-2.25,-1.75) L12(2.25,-1.75) L13(2.75,-1.75) L14(3.25,-1.75) M1(-3.25,-2.25) M2(-2.75,-2.25) M3(-2.25,-2.25) M4(-1.75,-2.25) M5(-1.25,-2.25) M6(-0.75,-2.25) M7(-0.25,-2.25) M8(0.25,-2.25) M9(0.75,-2.25) M10(1.25,-2.25) M11(1.75,-2.25) M12(2.25,-2.25) M13(2.75,-2.25) M14(3.25,-2.25) N1(-3.25,-2.75) N2(-2.75,-2.75) N3(-2.25,-2.75) N4(-1.75,-2.75) N5(-1.25,-2.75) N6(-0.75,-2.75) N7(-0.25,-2.75) N8(0.25,-2.75) N9(0.75,-2.75) N10(1.25,-2.75) N11(1.75,-2.75) N12(2.25,-2.75) N13(2.75,-2.75) N14(3.25,-2.75) P1(-3.25,-3.25) P2(-2.75,-3.25) P3(-2.25,-3.25) P4(-1.75,-3.25) P5(-1.25,-3.25) P6(-0.75,-3.25) P7(-0.25,-3.25) P8(0.25,-3.25) P9(0.75,-3.25) P10(1.25,-3.25) P11(1.75,-3.25) P12(2.25,-3.25) P13(2.75,-3.25) P14(3.25,-3.25)
FUSE_3P4X1P8
  rect 0.991x1.803 smd: 1(-1.25,0) 2(1.25,0)
HDR102_TMM
  rect 1.499x1.499 hole 0.889: 1(0,0)
  round 1.499 hole 0.889: 2(-2,0)
HDR203_TMM_210H
  rect 1.499x1.499 hole 0.889: 1(0,0)
  round 1.499 hole 0.889: 2(0,2) 3(2,0) 4(2,2) 5(4,0) 6(4,2)
HDR204_TMM_SM
  rect 3.302x1.016 smd: 1(-2.134,3.023) 2(2.134,3.023) 3(-2.134,1.016) 4(2.134,1.016) 5(-2.134,-1.016) 6(2.134,-1.016) 7(-2.134,-3.023) 8(2.134,-3.023)
HDR205_10M_50_SM_K
  rect 0.737x2.794 smd: 1(-2.54,-2.032) 2(-2.54,2.032) 3(-1.27,-2.032) 4(-1.27,2.032) 5(0,-2.032) 6(0,2.032) 7(1.27,-2.032) 8(1.27,2.032) 9(2.54,-2.032) 10(2.54,2.032)
HDR220_TSM_A_SM
  round 0 hole 1.727 unplated: (0,22.86) (0,-22.86)
  custom 0.318x0.318 smd: 1(-2.475,24.13) 2(2.475,24.13) 3(-2.475,21.59) 4(2.475,21.59) 37(-2.475,-21.59) 38(2.475,-21.59) 39(-2.475,-24.13) 40(2.475,-24.13)
  rect 3.683x1.27 smd: 5(-2.475,19.05) 6(2.475,19.05) 7(-2.475,16.51) 8(2.475,16.51) 9(-2.475,13.97) 10(2.475,13.97) 11(-2.475,11.43) 12(2.475,11.43) 13(-2.475,8.89) 14(2.475,8.89) 15(-2.475,6.35) 16(2.475,6.35) 17(-2.475,3.81) 18(2.475,3.81) 19(-2.475,1.27) 20(2.475,1.27) 21(-2.475,-1.27) 22(2.475,-1.27) 23(-2.475,-3.81) 24(2.475,-3.81) 25(-2.475,-6.35) 26(2.475,-6.35) 27(-2.475,-8.89) 28(2.475,-8.89) 29(-2.475,-11.43) 30(2.475,-11.43) 31(-2.475,-13.97) 32(2.475,-13.97) 33(-2.475,-16.51) 34(2.475,-16.51) 35(-2.475,-19.05) 36(2.475,-19.05)
HVQFN56_0P4_7X7_EP4P7MM
  rect 0.889x0.203 smd: 1(-3.45,2.6) 2(-3.45,2.2) 3(-3.45,1.8) 4(-3.45,1.4) 5(-3.45,1) 6(-3.45,0.6) 7(-3.45,0.2) 8(-3.45,-0.2) 9(-3.45,-0.6) 10(-3.45,-1) 11(-3.45,-1.4) 12(-3.45,-1.8) 13(-3.45,-2.2) 14(-3.45,-2.6) 29(3.45,-2.6) 30(3.45,-2.2) 31(3.45,-1.8) 32(3.45,-1.4) 33(3.45,-1) 34(3.45,-0.6) 35(3.45,-0.2) 36(3.45,0.2) 37(3.45,0.6) 38(3.45,1) 39(3.45,1.4) 40(3.45,1.8) 41(3.45,2.2) 42(3.45,2.6)
  rect 0.203x0.889 smd: 15(-2.6,-3.45) 16(-2.2,-3.45) 17(-1.8,-3.45) 18(-1.4,-3.45) 19(-1,-3.45) 20(-0.6,-3.45) 21(-0.2,-3.45) 22(0.2,-3.45) 23(0.6,-3.45) 24(1,-3.45) 25(1.4,-3.45) 26(1.8,-3.45) 27(2.2,-3.45) 28(2.6,-3.45) 43(2.6,3.45) 44(2.2,3.45) 45(1.8,3.45) 46(1.4,3.45) 47(1,3.45) 48(0.6,3.45) 49(0.2,3.45) 50(-0.2,3.45) 51(-0.6,3.45) 52(-1,3.45) 53(-1.4,3.45) 54(-1.8,3.45) 55(-2.2,3.45) 56(-2.6,3.45)
  rect 4.699x4.699 smd: 57(0,0)
HX2QFN16_0P4_2P7X2P7
  rect 0.813x0.203 smd: 1(-1.25,0.8) 2(-1.25,0.4) 3(-1.25,0) 4(-1.25,-0.4) 5(-1.25,-0.8) 9(1.25,-0.8) 10(1.25,-0.4) 11(1.25,0) 12(1.25,0.4) 13(1.25,0.8)
  rect 0.203x0.813 smd: 6(-0.4,-1.25) 7(0,-1.25) 8(0.4,-1.25) 14(0.4,1.25) 15(0,1.25) 16(-0.4,1.25)
  rect 1.194x1.092 smd: 17(0,0)
IND_0603
  rect 0.991x0.813 smd: 1(-0.69,0) 2(0.69,0)
IND_2016A
  rect 0.864x1.803 smd: 1(-0.835,0) 2(0.835,0)
IND_DLW43
  rect 0.914x0.914 smd: 1(-2,1.25) 2(2,1.25) 3(2,-1.25) 4(-2,-1.25)
IND_IHLP
  rect 2.007x3.429 smd: 1(-2.794,0) 2(2.743,0)
IND_SPH2520
  rect 1.219x2.007 smd: 1(-1.01,0) 2(1.01,0)
LED4_3P4X3_SM
  rect 0.991x1.803 smd: 1(0.75,1.7) 2(0.75,-1.7) 3(-0.75,-1.7) 4(-0.75,1.7)
LED_0603
  rect 0.838x0.787 smd: A(-0.775,0) C(0.775,0)
LED_0603_11MIL
  rect 0.838x0.787 smd: A(-0.775,0) C(0.775,0)
LGA8_3P1X4P1MM_SPK0641
  rect 0.508x1.016 smd: 1(-0.425,-0.675) 2(-0.425,0.675) 3(0.425,0.675) 4(0.425,-0.675)
  rect 1.321x0.406 smd: 5(0,-1.75) 7(0,1.75)
  rect 0.406x2.311 smd: 6(-1.25,0) 8(1.25,0)
LGA14_0P5_3X2P5
  rect 0.457x0.254 smd: 1(-1.175,0.75) 2(-1.175,0.25) 3(-1.175,-0.25) 4(-1.175,-0.75) 8(1.175,-0.75) 9(1.175,-0.25) 10(1.175,0.25) 11(1.175,0.75)
  rect 0.254x0.457 smd: 5(-0.5,-0.925) 6(0,-0.925) 7(0.5,-0.925) 12(0.5,0.925) 13(0,0.925) 14(-0.5,0.925)
LQFP64_0P5_10X10
  rect 1.372x0.279 smd: 1(-5.775,3.75) 2(-5.775,3.25) 3(-5.775,2.75) 4(-5.775,2.25) 5(-5.775,1.75) 6(-5.775,1.25) 7(-5.775,0.75) 8(-5.775,0.25) 9(-5.775,-0.25) 10(-5.775,-0.75) 11(-5.775,-1.25) 12(-5.775,-1.75) 13(-5.775,-2.25) 14(-5.775,-2.75) 15(-5.775,-3.25) 16(-5.775,-3.75) 33(5.775,-3.75) 34(5.775,-3.25) 35(5.775,-2.75) 36(5.775,-2.25) 37(5.775,-1.75) 38(5.775,-1.25) 39(5.775,-0.75) 40(5.775,-0.25) 41(5.775,0.25) 42(5.775,0.75) 43(5.775,1.25) 44(5.775,1.75) 45(5.775,2.25) 46(5.775,2.75) 47(5.775,3.25) 48(5.775,3.75)
  rect 0.279x1.372 smd: 17(-3.75,-5.775) 18(-3.25,-5.775) 19(-2.75,-5.775) 20(-2.25,-5.775) 21(-1.75,-5.775) 22(-1.25,-5.775) 23(-0.75,-5.775) 24(-0.25,-5.775) 25(0.25,-5.775) 26(0.75,-5.775) 27(1.25,-5.775) 28(1.75,-5.775) 29(2.25,-5.775) 30(2.75,-5.775) 31(3.25,-5.775) 32(3.75,-5.775) 49(3.75,5.775) 50(3.25,5.775) 51(2.75,5.775) 52(2.25,5.775) 53(1.75,5.775) 54(1.25,5.775) 55(0.75,5.775) 56(0.25,5.775) 57(-0.25,5.775) 58(-0.75,5.775) 59(-1.25,5.775) 60(-1.75,5.775) 61(-2.25,5.775) 62(-2.75,5.775) 63(-3.25,5.775) 64(-3.75,5.775)
MH142P080
  round 3.607 hole 2.032: 1(0,0)
MH244-166T_202H
  round 6.198 hole 4.216: 1(0,0)
PQFN16_0P4_2P65X1P85
  rect 0.203x0.762 smd: 1(-0.6,-0.724)
  rect 0.203x0.66 smd: 2(-0.2,-0.775) 3(0.2,-0.775) 4(0.6,-0.775) 9(0.6,0.775) 10(0.2,0.775) 11(-0.2,0.775) 12(-0.6,0.775)
  rect 0.66x0.203 smd: 5(1.21,-0.6) 6(1.21,-0.2) 7(1.21,0.2) 8(1.21,0.6) 13(-1.21,0.6) 14(-1.21,0.2) 15(-1.21,-0.2) 16(-1.21,-0.6)
QFN12_0P5_2X3MM_EP
  rect 0.711x0.254 smd: 1(-0.95,0.5) 2(-0.95,0) 3(-0.95,-0.5) 7(0.95,-0.5) 8(0.95,0) 9(0.95,0.5)
  rect 0.254x0.914 smd: 4(-0.5,-1.35) 5(0,-1.35) 6(0.5,-1.35)
  custom 0.225x0.225 smd: 10(0,1.35)
  rect 0.406x0.254 smd: 11(0,0)
QFN12_0P5_3P1X2P1
  rect 0.254x1.499 smd: 1(0.5,0.55) 2(-0.5,0.55) 7(0,-0.55)
  rect 0.711x0.254 smd: 3(-1.45,0.75) 4(-1.45,0.25) 5(-1.45,-0.25) 6(-1.45,-0.75) 9(1.45,-0.75) 10(1.45,-0.25) 11(1.45,0.25) 12(1.45,0.75)
  rect 0.254x0.711 smd: 8(0.5,-0.95)
QFN24_4X4_EP2P25MM
  oval 0.279x0.813 smd: 1(-1.25,-1.956) 2(-0.75,-1.956) 3(-0.25,-1.956) 4(0.25,-1.956) 5(0.75,-1.956) 6(1.25,-1.956) 13(1.25,1.956) 14(0.75,1.956) 15(0.25,1.956) 16(-0.25,1.956) 17(-0.75,1.956) 18(-1.25,1.956)
  oval 0.813x0.279 smd: 7(1.956,-1.25) 8(1.956,-0.75) 9(1.956,-0.25) 10(1.956,0.25) 11(1.956,0.75) 12(1.956,1.25) 19(-1.956,1.25) 20(-1.956,0.75) 21(-1.956,0.25) 22(-1.956,-0.25) 23(-1.956,-0.75) 24(-1.956,-1.25)
  rect 2.235x2.235 smd: 25(0,0)
QFN40_0P4_5X5MM
  oval 0.813x0.203 smd: 1(-2.46,1.8) 10(-2.46,-1.8) 21(2.46,-1.8) 30(2.46,1.8)
  rect 0.813x0.203 smd: 2(-2.46,1.4) 3(-2.46,1) 4(-2.46,0.6) 5(-2.46,0.2) 6(-2.46,-0.2) 7(-2.46,-0.6) 8(-2.46,-1) 9(-2.46,-1.4) 22(2.46,-1.4) 23(2.46,-1) 24(2.46,-0.6) 25(2.46,-0.2) 26(2.46,0.2) 27(2.46,0.6) 28(2.46,1) 29(2.46,1.4)
  oval 0.203x0.813 smd: 11(-1.8,-2.46) 20(1.8,-2.46) 31(1.8,2.46) 40(-1.8,2.46)
  rect 0.203x0.813 smd: 12(-1.4,-2.46) 13(-1,-2.46) 14(-0.6,-2.46) 15(-0.2,-2.46) 16(0.2,-2.46) 17(0.6,-2.46) 18(1,-2.46) 19(1.4,-2.46) 32(1.4,2.46) 33(1,2.46) 34(0.6,2.46) 35(0.2,2.46) 36(-0.2,2.46) 37(-0.6,2.46) 38(-1,2.46) 39(-1.4,2.46)
  rect 3.607x3.607 smd: 41(0,0)
RC0402_25
  round 0.635 smd: 1(-0.508,0) 2(0.508,0)
RC0805_OV
  oval 0.889x1.524 smd: 1(-0.965,0) 2(0.965,0)
SC70-5
  rect 0.406x0.813 smd: 1(-0.65,-1.079) 2(0,-1.079) 3(0.65,-1.079) 4(0.65,1.079) 5(-0.65,1.079)
SC70_3
  rect 0.711x0.889 smd: 1(-0.648,-0.952) 2(0.648,-0.952) 3(0,0.952)
SKT_BGA208_0P5_17P725SQ_ELAST
  round 0 hole 1.702 unplated: (-6.362,6.363) (-6.362,-6.363) (6.362,6.363) (6.362,-6.363)
  round 0 hole 0.848 unplated: (-6.362,-1.282) (6.362,3.822)
  round 0.254 smd: A1(-3.75,4) A2(-3.25,4) A3(-2.75,4) A4(-2.25,4) A5(-1.75,4) A6(-1.25,4) A7(-0.75,4) A8(-0.25,4) A9(0.25,4) A10(0.75,4) A11(1.25,4) A12(1.75,4) A13(2.25,4) A14(2.75,4) A15(3.25,4) A16(3.75,4) A17(4.25,4) B1(-3.75,3.5) B2(-3.25,3.5) B3(-2.75,3.5) B4(-2.25,3.5) B5(-1.75,3.5) B6(-1.25,3.5) B7(-0.75,3.5) B8(-0.25,3.5) B9(0.25,3.5) B10(0.75,3.5) B11(1.25,3.5) B12(1.75,3.5) B13(2.25,3.5) B14(2.75,3.5) B15(3.25,3.5) B16(3.75,3.5) B17(4.25,3.5) C1(-3.75,3) C2(-3.25,3) C4(-2.25,3) C6(-1.25,3) C8(-0.25,3) C9(0.25,3) C10(0.75,3) C12(1.75,3) C14(2.75,3) C16(3.75,3) C17(4.25,3) D1(-3.75,2.5) D2(-3.25,2.5) D3(-2.75,2.5) D4(-2.25,2.5) D6(-1.25,2.5) D8(-0.25,2.5) D10(0.75,2.5) D12(1.75,2.5) D14(2.75,2.5) D15(3.25,2.5) D16(3.75,2.5) D17(4.25,2.5) E1(-3.75,2) E2(-3.25,2) E6(-1.25,2) E8(-0.25,2) E10(0.75,2) E12(1.75,2) E16(3.75,2) E17(4.25,2) F1(-3.75,1.5) F2(-3.25,1.5) F3(-2.75,1.5) F4(-2.25,1.5) F5(-1.75,1.5) F6(-1.25,1.5) F8(-0.25,1.5) F10(0.75,1.5) F12(1.75,1.5) F13(2.25,1.5) F14(2.75,1.5) F15(3.25,1.5) F16(3.75,1.5) F17(4.25,1.5) G1(-3.75,1) G2(-3.25,1) G6(-1.25,1) G7(-0.75,1) G9(0.25,1) G11(1.25,1) G12(1.75,1) G16(3.75,1) G17(4.25,1) H1(-3.75,0.5) H2(-3.25,0.5) H3(-2.75,0.5) H4(-2.25,0.5) H5(-1.75,0.5) H7(-0.75,0.5) H9(0.25,0.5) H11(1.25,0.5) H13(2.25,0.5) H14(2.75,0.5) H15(3.25,0.5) H16(3.75,0.5) H17(4.25,0.5) J1(-3.75,0) J2(-3.25,0) J6(-1.25,0) J12(1.75,0) J16(3.75,0) J17(4.25,0) K1(-3.75,-0.5) K2(-3.25,-0.5) K3(-2.75,-0.5) K4(-2.25,-0.5) K5(-1.75,-0.5) K7(-0.75,-0.5) K9(0.25,-0.5) K11(1.25,-0.5) K13(2.25,-0.5) K14(2.75,-0.5) K15(3.25,-0.5) K16(3.75,-0.5) K17(4.25,-0.5) L1(-3.75,-1) L2(-3.25,-1) L6(-1.25,-1) L7(-0.75,-1) L9(0.25,-1) L11(1.25,-1) L12(1.75,-1) L16(3.75,-1) L17(4.25,-1) M1(-3.75,-1.5) M2(-3.25,-1.5) M3(-2.75,-1.5) M4(-2.25,-1.5) M5(-1.75,-1.5) M6(-1.25,-1.5) M8(-0.25,-1.5) M10(0.75,-1.5) M12(1.75,-1.5) M13(2.25,-1.5) M14(2.75,-1.5) M15(3.25,-1.5) M16(3.75,-1.5) M17(4.25,-1.5) N1(-3.75,-2) N2(-3.25,-2) N6(-1.25,-2) N8(-0.25,-2) N10(0.75,-2) N12(1.75,-2) N16(3.75,-2) N17(4.25,-2) P1(-3.75,-2.5) P2(-3.25,-2.5) P3(-2.75,-2.5) P4(-2.25,-2.5) P6(-1.25,-2.5) P8(-0.25,-2.5) P10(0.75,-2.5) P12(1.75,-2.5) P14(2.75,-2.5) P15(3.25,-2.5) P16(3.75,-2.5) P17(4.25,-2.5) R1(-3.75,-3) R2(-3.25,-3) R4(-2.25,-3) R6(-1.25,-3) R8(-0.25,-3) R9(0.25,-3) R10(0.75,-3) R12(1.75,-3) R14(2.75,-3) R16(3.75,-3) R17(4.25,-3) T1(-3.75,-3.5) T2(-3.25,-3.5) T3(-2.75,-3.5) T4(-2.25,-3.5) T5(-1.75,-3.5) T6(-1.25,-3.5) T7(-0.75,-3.5) T8(-0.25,-3.5) T9(0.25,-3.5) T10(0.75,-3.5) T11(1.25,-3.5) T12(1.75,-3.5) T13(2.25,-3.5) T14(2.75,-3.5) T15(3.25,-3.5) T16(3.75,-3.5) T17(4.25,-3.5) U1(-3.75,-4) U2(-3.25,-4) U3(-2.75,-4) U4(-2.25,-4) U5(-1.75,-4) U6(-1.25,-4) U7(-0.75,-4) U8(-0.25,-4) U9(0.25,-4) U10(0.75,-4) U11(1.25,-4) U12(1.75,-4) U13(2.25,-4) U14(2.75,-4) U15(3.25,-4) U16(3.75,-4) U17(4.25,-4)
SO8_1P27_4X5
  rect 1.6x0.61 smd: 1(-2.7,1.905) 2(-2.7,0.635) 3(-2.7,-0.635) 4(-2.7,-1.905) 5(2.7,-1.905) 6(2.7,-0.635) 7(2.7,0.635) 8(2.7,1.905)
SO16_0P5_3P5X4P5_MM
  rect 0.889x0.279 smd: 1(-1.7,1.75) 2(-1.7,1.25) 3(-1.7,0.75) 4(-1.7,0.25) 5(-1.7,-0.25) 6(-1.7,-0.75) 7(-1.7,-1.25) 8(-1.7,-1.75) 9(1.7,-1.75) 10(1.7,-1.25) 11(1.7,-0.75) 12(1.7,-0.25) 13(1.7,0.25) 14(1.7,0.75) 15(1.7,1.25) 16(1.7,1.75)
  rect 2x3.8 smd: 17(0,0)
SOD323
  rect 0.889x1.219 smd: A(0,1.27) C(0,-1.27)
SOD523
  rect 0.61x0.813 smd: A(0.85,0) C(-0.85,0)
SOT23-5
  rect 0.61x1.118 smd: 1(-0.95,-1.425) 2(0,-1.425) 3(0.95,-1.425) 4(0.95,1.425) 5(-0.95,1.425)
SOT23-6
  rect 0.61x1.118 smd: 1(-0.95,-1.321) 2(0,-1.321) 3(0.95,-1.321) 4(0.95,1.321) 5(0,1.321) 6(-0.95,1.321)
SOT23_A
  rect 0.787x0.889 smd: 1(-0.94,-1.003) 2(0.94,-1.003) 3(0,1.003)
SOT25
  rect 0.559x0.813 smd: 1(0.95,1.2) 2(0,1.2) 3(-0.95,1.2) 4(-0.95,-1.2) 5(0.95,-1.2)
SOT753_5P_1P7X3P1MM
  rect 1.321x0.406 smd: 1(-1.175,0.95) 2(-1.175,0) 3(-1.175,-0.95) 4(1.175,-0.95) 5(1.175,0.95)
SOT-23
  rect 1.016x1.397 smd: 1(-0.95,-1.1) 2(0.95,-1.1) 3(0,1.1)
SOT-23-5
  rect 0.686x0.991 smd: 1(-0.953,-1.295) 2(0,-1.295) 3(0.953,-1.295) 4(0.953,1.295) 5(-0.953,1.295)
SSOP8_DCU
  rect 0.279x1.219 smd: 1(-0.75,-1.499) 2(-0.25,-1.499) 3(0.25,-1.499) 4(0.75,-1.499) 5(0.75,1.499) 6(0.25,1.499) 7(-0.25,1.499) 8(-0.75,1.499)
SW4_SPST_4P6X2P8_SM
  rect 0.914x1.016 smd: 1(-2.08,-0.8) 2(2.08,-0.8) 3(-2.08,0.8) 4(2.08,0.8)
SW6_DPDT_M096H_TH
  rect 1.346x1.346 hole 0.711: 1(0,0)
  round 1.346 hole 0.711: 2(0,-2.5) 3(0,-5) 4(3.2,0) 5(3.2,-2.5) 6(3.2,-5)
SW_2P8X5P7_SM
  rect 1.016x1.6 smd: 1(0,2.54) 2(0,-2.54)
SW_CHS_04_A
  rect 1.6x0.762 smd: 1(-2.54,1.905) 2(2.54,1.905) 3(-2.54,0.635) 4(2.54,0.635) 5(-2.54,-0.635) 6(2.54,-0.635) 7(-2.54,-1.905) 8(2.54,-1.905)
TESTPOINT_35MIL
  round 0.889 smd: 1(0,0)
TP_TH_018
  round 0.914 hole 0.457: 1(0,0)
TP_TH_063
  round 2.311 hole 1.6: 1(0,0)
TPAD_015
  round 0.381 smd: 1(0,0)
TPAD_020
  round 0.508 smd: 1(0,0)
TPAD_050
  round 1.27 smd: 1(0,0)
UDFN6_1X1P5MM
  rect 0.584x0.305 smd: 1(-0.418,0.5)
  rect 0.508x0.305 smd: 2(-0.38,0) 3(-0.38,-0.5) 4(0.38,-0.5) 5(0.38,0) 6(0.38,0.5)
unnamed#2
  round 1.016 smd: (0,0)
UQFN12_1P7X2MM
  rect 0.686x0.305 smd: 1(-0.655,0.84)
  rect 0.69x0.22 smd: 2(-0.655,0.4) 3(-0.655,0) 4(-0.655,-0.4) 5(-0.655,-0.8) 7(0.655,-0.8) 8(0.655,-0.4) 9(0.655,0) 10(0.655,0.4) 11(0.655,0.8)
  rect 0.22x0.69 smd: 6(0,-0.805) 12(0,0.805)
UQFN32_0P5_5X5_EP3X3
  rect 0.914x0.279 smd: 1(-2.55,1.75) 2(-2.55,1.25) 3(-2.55,0.75) 4(-2.55,0.25) 5(-2.55,-0.25) 6(-2.55,-0.75) 7(-2.55,-1.25) 8(-2.55,-1.75) 17(2.55,-1.75) 18(2.55,-1.25) 19(2.55,-0.75) 20(2.55,-0.25) 21(2.55,0.25) 22(2.55,0.75) 23(2.55,1.25) 24(2.55,1.75)
  rect 0.279x0.914 smd: 9(-1.75,-2.55) 10(-1.25,-2.55) 11(-0.75,-2.55) 12(-0.25,-2.55) 13(0.25,-2.55) 14(0.75,-2.55) 15(1.25,-2.55) 16(1.75,-2.55) 25(1.75,2.55) 26(1.25,2.55) 27(0.75,2.55) 28(0.25,2.55) 29(-0.25,2.55) 30(-0.75,2.55) 31(-1.25,2.55) 32(-1.75,2.55)
  rect 2.997x2.997 smd: 33(0,0)
USB6P_TYPEC_RA_SM
  round 0 hole 0.95 unplated: (-3.25,1.275) (3.25,1.275)
  rect 0.711x1.397 smd: A5(-0.5,3.245) B5(0.5,3.245)
  rect 0.762x1.397 smd: A9(1.52,3.245) B9(-1.52,3.245)
  rect 0.813x1.397 smd: A12(2.75,3.245) B12(-2.75,3.245)
  oval 0.889x1.575 hole 0.508x1.194: SH1(-4.895,1.275) SH2(4.895,1.275) SH3(-4.895,-1.725) SH4(4.895,-1.725)
WLCSP4_0P5_0P99X0P99
  round 0.254 smd: A1(-0.25,0.25) A2(0.25,0.25) B1(-0.25,-0.25) B2(0.25,-0.25)
WLCSP5_0P4_0P82X1P22
  round 0.254 smd: A1(-0.2,0.4) A2(0.2,0.4) B1(0,0) C1(-0.2,-0.4) C2(0.2,-0.4)
WLCSP6_0P4_0P84X1P18
  round 0.24 smd: A1(-0.2,0.4) A2(0.2,0.4) B1(-0.2,0) B2(0.2,0) C1(-0.2,-0.4) C2(0.2,-0.4)
WLCSP12_0P4_1P3X1P7MM_SMDP
  round 0.254 smd: A1(-0.4,0.6) A2(0,0.6) A3(0.4,0.6) B1(-0.4,0.2) B2(0,0.2) B3(0.4,0.2) C1(-0.4,-0.2) C2(0,-0.2) C3(0.4,-0.2) D1(-0.4,-0.6) D2(0,-0.6) D3(0.4,-0.6)
WLCSP15_0P5_1P57X2P59
  round 0.254 smd: A1(0.5,1) A2(0,1) A3(-0.5,1) B1(0.5,0.5) B2(0,0.5) B3(-0.5,0.5) C1(0.5,0) C2(0,0) C3(-0.5,0) D1(0.5,-0.5) D2(0,-0.5) D3(-0.5,-0.5) E1(0.5,-1) E2(0,-1) E3(-0.5,-1)
WLCSP42_0P4_2P94X2P54_SMDP
  round 0.254 smd: A1(-1,1.2) A2(-0.6,1.2) A3(-0.2,1.2) A4(0.2,1.2) A5(0.6,1.2) A6(1,1.2) B1(-1,0.8) B2(-0.6,0.8) B3(-0.2,0.8) B4(0.2,0.8) B5(0.6,0.8) B6(1,0.8) C1(-1,0.4) C2(-0.6,0.4) C3(-0.2,0.4) C4(0.2,0.4) C5(0.6,0.4) C6(1,0.4) D1(-1,0) D2(-0.6,0) D3(-0.2,0) D4(0.2,0) D5(0.6,0) D6(1,0) E1(-1,-0.4) E2(-0.6,-0.4) E3(-0.2,-0.4) E4(0.2,-0.4) E5(0.6,-0.4) E6(1,-0.4) F1(-1,-0.8) F2(-0.6,-0.8) F3(-0.2,-0.8) F4(0.2,-0.8) F5(0.6,-0.8) F6(1,-0.8) G1(-1,-1.2) G2(-0.6,-1.2) G3(-0.2,-1.2) G4(0.2,-1.2) G5(0.6,-1.2) G6(1,-1.2)
XQFN12_0P4_1P8X2P1
  rect 0.66x0.305 smd: 1(-0.675,0.85)
  rect 0.66x0.203 smd: 2(-0.675,0.4) 3(-0.675,0) 4(-0.675,-0.4) 5(-0.675,-0.8) 7(0.675,-0.8) 8(0.675,-0.4) 9(0.675,0) 10(0.675,0.4) 11(0.675,0.8)
  rect 0.203x0.66 smd: 6(0,-0.825) 12(0,0.825)
XQFN16_0P4_2P7X1P9
  rect 0.203x0.965 smd: 1(-0.6,-0.625) 2(-0.2,-0.625) 3(0.2,-0.625) 4(0.6,-0.625) 9(0.6,0.625) 10(0.2,0.625) 11(-0.2,0.625) 12(-0.6,0.625)
  rect 0.66x0.203 smd: 5(1.21,-0.6) 6(1.21,-0.2) 7(1.21,0.2) 8(1.21,0.6) 13(-1.21,0.6) 14(-1.21,0.2) 15(-1.21,-0.2) 16(-1.21,-0.6)
XSON10_0P5_1P1X2P6MM
  rect 0.711x0.254 smd: 1(-0.457,1) 2(-0.457,0.5) 3(-0.457,0) 4(-0.457,-0.5) 5(-0.457,-1) 6(0.457,-1) 7(0.457,-0.5) 8(0.457,0) 9(0.457,0.5) 10(0.457,1)
XTAL2-3P2X1P5-SM
  rect 1.092x1.905 smd: 1(-1.25,0) 2(1.25,0)
XTAL_4_3P3X2P6MM
  rect 1.397x1.194 smd: 1(-1.1,-0.85) 2(1.1,-0.85) 3(1.1,0.85) 4(-1.1,0.85)
XTL4_2P5X2MM_SM
  rect 0.991x0.889 smd: 1(-0.925,-0.775) 2(0.925,-0.775) 3(0.925,0.775) 4(-0.925,0.775)
XTLOSC4_3P2X2P5MM_SM
  rect 1.397x1.194 smd: 1(-1.1,-0.8) 2(1.1,-0.8) 3(1.1,0.8) 4(-1.1,0.8)

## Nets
5V_PG: TP903.1(PIN1) U901.3
